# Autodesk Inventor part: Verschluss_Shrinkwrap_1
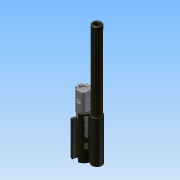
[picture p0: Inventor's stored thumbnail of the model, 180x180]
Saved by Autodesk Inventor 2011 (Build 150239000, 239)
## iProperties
Created: 2012-08
Part Number: Verschluss_Shrinkwrap_1
Document SubType Name: Modeling
Designer: Oscar1
Density: 1 g/cm^3
Author: Oscar1
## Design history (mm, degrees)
derived "Verschluss.iam"
body "Solid1"
node "Verschlussträger.ipt:1"
sketch "Steuerstück.ipt:1"
sketch "Schlagbolzen.ipt:1"
sketch "Verschlusskopf.ipt:1"
sketch "Rollenhalter.ipt:1"
sketch "Verschlussrolle.ipt:1"
sketch "Verschlussrolle.ipt:2"
sketch "ISO 8734 - 3 x 24 - ADIN EN (1):1"
sketch "Verschlusshaltefeder.ipt:1"
sketch "Verschlussklammer.ipt:1"
sketch "Patronenhalter.ipt:1"
sketch "Patronenfeder.ipt:1"
body "Solid2"
body "Solid3"
body "Solid4"
body "Solid5"
body "Solid6"
body "Solid7"
body "Solid8"
body "Solid9"
body "Solid10"
body "Solid11"
body "Solid12"
